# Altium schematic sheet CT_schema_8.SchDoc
size 274 x 160 mm
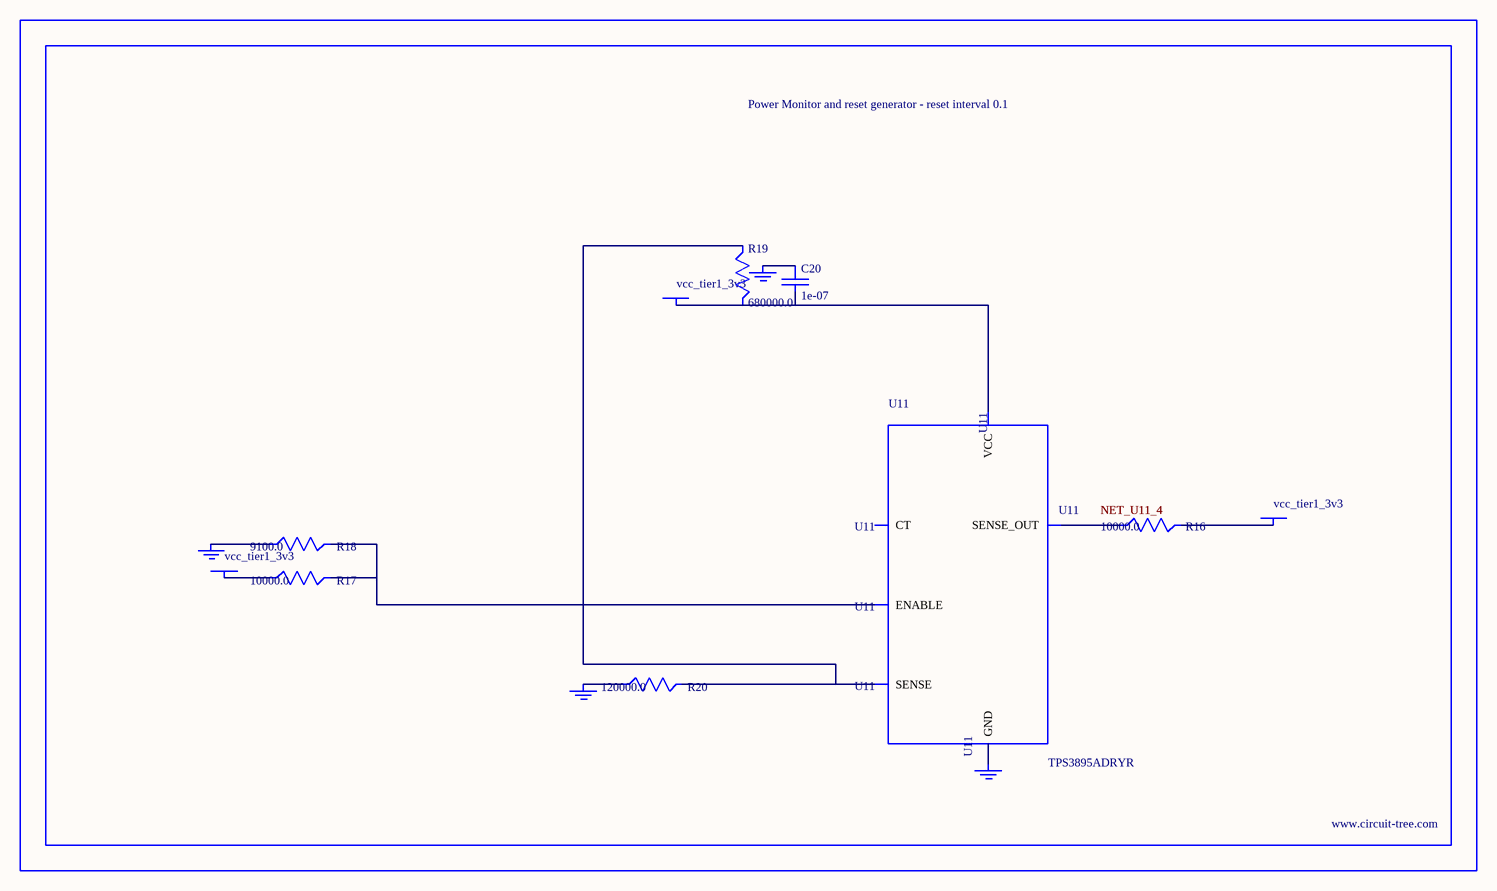
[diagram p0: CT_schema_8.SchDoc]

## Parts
BORDER7  (no value)
C20  1e-07  [C0402]
GND_INSTANCE_7_0  (no value)
GND_INSTANCE_7_1  (no value)
GND_INSTANCE_7_2  (no value)
GND_INSTANCE_7_3  (no value)
POWER_INSTANCE_7_0  vcc_tier1_3v3
POWER_INSTANCE_7_1  vcc_tier1_3v3
POWER_INSTANCE_7_2  vcc_tier1_3v3
R16  10000.0  [R0603]
R17  10000.0  [R0603]
R18  9100.0  [R0603]
R19  680000.0  [R0603]
R20  120000.0  [R0603]
U11  TPS3895ADRYR  [SON-6]

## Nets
NetC20_1: C20.1 GND_INSTANCE_7_2.0(GND)
NetC20_2: C20.2 POWER_INSTANCE_7_2.0(PWR) R19.2 U11.6(VCC)
NetGND_INSTANCE_7_0_0: GND_INSTANCE_7_0.0(GND) R18.1
NetGND_INSTANCE_7_1_0: GND_INSTANCE_7_1.0(GND) R20.1
NetGND_INSTANCE_7_3_0: GND_INSTANCE_7_3.0(GND) U11.2(GND)
NetPOWER_INSTANCE_7_0_0: POWER_INSTANCE_7_0.0(PWR) R17.1
NetPOWER_INSTANCE_7_1_0: POWER_INSTANCE_7_1.0(PWR) R16.2
NetR16_1: R16.1 U11.4(SENSE_OUT)
NetR17_2: R17.2 R18.2 U11.1(ENABLE)
NetR19_1: R19.1 R20.2 U11.3(SENSE)

Not connected (* = marked no-connect by the designer): U11 5(CT)

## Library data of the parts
BORDER7 = BORDER_PAGE7
C20 = C0402C104K3RACTU
GND_INSTANCE_7_0-GND_INSTANCE_7_3 = GND
POWER_INSTANCE_7_0-POWER_INSTANCE_7_2 = PWR
R16 R17 = RC0603JR-0710KL
R18 = RC0603JR-079K1L
R19 = RC0603JR-07680KL
R20 = RC0603JR-07120KL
